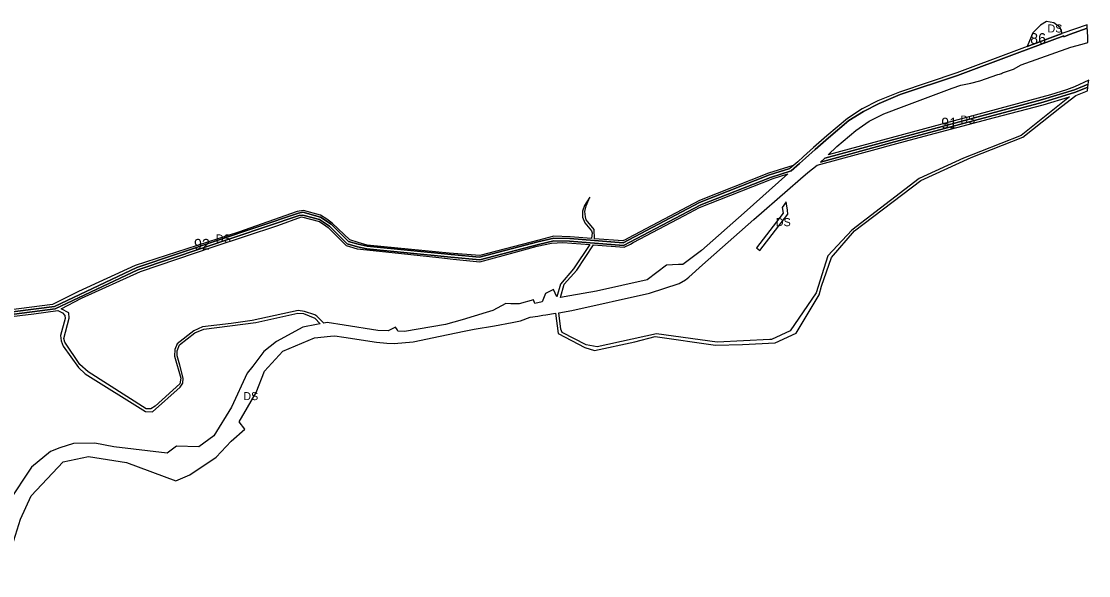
# Model space of a CAD drawing. Extents: x -477304 to -465641, y -1159113 to -1149285.
# Drawn here: x -466842 to -465641, y -1153111 to -1152488 of the extents above; entities that cross this region are included whole.
import ezdxf

# ---------------------------------------------------------------- set-up
doc = ezdxf.new("R2010")
doc.units = 0
for name, color, linetype in [('14', 7, 'Continuous'), ('35', 7, 'Continuous'), ('60', 7, 'Continuous')]:
    doc.layers.add(name, color=color, linetype=linetype)

msp = doc.modelspace()

# ---------------------------------------------------------------- linework, layer by layer
at = {"layer": '14'}
for p, q in [((-465710.6, -1152516.1), (-465671.1, -1152501.3)), ((-465643, -1152494.7), (-465643.1, -1152491.6)), ((-465669.3, -1152505.1), (-465662.8, -1152502.6)), ((-465669.2, -1152503.8), (-465669.3, -1152505.1)), ((-465642.2, -1152561.6), (-465641.9, -1152558.2)), ((-465938.3, -1152641.5), (-465943.1, -1152645.9))]:
    msp.add_line(p, q, dxfattribs=at)
for points in [[(-465671.1, -1152501.3), (-465673.6, -1152494.6), (-465680.5, -1152489.2), (-465688.7, -1152487.7), (-465695.6, -1152491.8), (-465704.3, -1152500.6), (-465710.6, -1152516.1)], [(-465643.1, -1152491.6), (-465670.3, -1152501), (-465789.9, -1152545.7), (-465854.4, -1152567.3), (-465878.5, -1152577.1), (-465896.4, -1152586.2), (-465912.9, -1152596.9), (-465936.1, -1152616.3), (-465951.1, -1152629.7), (-465962.1, -1152639.5), (-465968.7, -1152645.5), (-465977.5, -1152653.2)], [(-465662.8, -1152502.6), (-465643, -1152495.3), (-465643, -1152494.7)], [(-465976, -1152655.9), (-465966.7, -1152647.7), (-465960.1, -1152641.7), (-465949.1, -1152631.9), (-465934.2, -1152618.6), (-465911.1, -1152599.3), (-465894.9, -1152588.9), (-465877.2, -1152579.9), (-465853.4, -1152570.1), (-465788.9, -1152548.5), (-465721.8, -1152523.4), (-465669.2, -1152503.8)], [(-465641.9, -1152558.2), (-465657.3, -1152564.7), (-465693.5, -1152575.7), (-465864.7, -1152621.6), (-465938.3, -1152641.5)], [(-465943.1, -1152645.9), (-465863.9, -1152624.4), (-465692.7, -1152578.6), (-465656.2, -1152567.5), (-465642.2, -1152561.6)], [(-465977.5, -1152653.2), (-466000.4, -1152660.4), (-466079.1, -1152691.4), (-466165.2, -1152736.6), (-466225.2, -1152732), (-466243.2, -1152731.6), (-466261, -1152735.6), (-466326.7, -1152752.9), (-466358.7, -1152750), (-466453.2, -1152740.5), (-466463.2, -1152738.4), (-466474, -1152735.2), (-466493.5, -1152715.7), (-466505.4, -1152707.9), (-466525.3, -1152702.4), (-466530.3, -1152703.2), (-466712.1, -1152764.4), (-466804.8, -1152808.2), (-466914.5, -1152822.2)], [(-466914, -1152825.2), (-466803.9, -1152811.1), (-466710.9, -1152767.2), (-466529.6, -1152706.1), (-466525.4, -1152705.5), (-466506.6, -1152710.6), (-466495.4, -1152718.1), (-466475.6, -1152737.8), (-466463.9, -1152741.4), (-466453.6, -1152743.5), (-466358.9, -1152753), (-466326.5, -1152756), (-466260.3, -1152738.5), (-466242.9, -1152734.6), (-466225.4, -1152735), (-466164.6, -1152739.6), (-466077.9, -1152694.1), (-465999.4, -1152663.2), (-465976, -1152655.9)]]:
    msp.add_lwpolyline(points, dxfattribs=at)
at = {"layer": '35'}
for p, q in [((-465662.8, -1152502.6), (-465669.3, -1152505.1)), ((-465669.3, -1152505.1), (-465669.2, -1152503.8)), ((-465661.4, -1152516.9), (-465648.6, -1152513.3)), ((-465648.6, -1152513.3), (-465642.2, -1152511.5)), ((-465717.2, -1152536.5), (-465661.4, -1152516.9)), ((-465725.8, -1152541.4), (-465717.2, -1152536.5)), ((-465743.5, -1152547.6), (-465741.8, -1152547)), ((-465738.2, -1152545.7), (-465725.8, -1152541.4)), ((-465794.9, -1152563), (-465785.1, -1152559.3)), ((-465657.5, -1152561.5), (-465666.5, -1152564.7)), ((-465641.4, -1152553.9), (-465657.5, -1152561.5)), ((-465641.9, -1152558.2), (-465641.4, -1152553.9)), ((-465684.4, -1152570.4), (-465934.5, -1152637.9)), ((-465849, -1152583), (-465794.9, -1152563)), ((-465662.9, -1152572.7), (-465717.3, -1152616)), ((-465666.5, -1152564.7), (-465684.4, -1152570.4)), ((-465671.9, -1152583.3), (-465656, -1152570.9)), ((-465656, -1152570.9), (-465642.6, -1152565.8)), ((-465642.6, -1152565.8), (-465642.2, -1152561.6)), ((-465871.9, -1152591.8), (-465849, -1152583)), ((-465894.9, -1152588.9), (-465911.1, -1152599.3)), ((-465765.7, -1152600.6), (-465747.2, -1152595.8)), ((-465911.1, -1152599.3), (-465934.2, -1152618.6)), ((-465717.3, -1152616), (-465763.1, -1152633.9)), ((-465946.9, -1152649.4), (-465876.3, -1152630.3)), ((-465934.5, -1152637.9), (-465924.7, -1152628.4)), ((-465876.3, -1152630.3), (-465867, -1152627.8)), ((-465943.1, -1152645.9), (-465938.3, -1152641.5)), ((-465782.2, -1152641.6), (-465832.2, -1152664.3)), ((-465830.3, -1152666.7), (-465773.7, -1152640.9)), ((-465763.1, -1152633.9), (-465782.2, -1152641.6)), ((-465973.7, -1152649.8), (-466001.7, -1152658.4)), ((-465977.5, -1152653.2), (-465973.7, -1152649.8)), ((-465957.4, -1152657.8), (-465946.9, -1152649.4)), ((-465979.9, -1152659.3), (-466029, -1152703)), ((-465980.3, -1152677.6), (-465965.5, -1152664.6)), ((-465965.5, -1152664.6), (-465957.4, -1152657.8)), ((-465904.7, -1152723.4), (-465830.3, -1152666.7)), ((-466202.5, -1152685.4), (-466208.5, -1152694.7)), ((-465980.4, -1152700.1), (-465981.8, -1152690.7)), ((-466029, -1152703), (-466076.8, -1152745.3)), ((-466011.4, -1152745.3), (-465979.9, -1152704.6)), ((-465979.9, -1152704.6), (-465980.4, -1152700.1)), ((-466626.4, -1152741.4), (-466553.4, -1152717.2)), ((-466492.6, -1152714.6), (-466498.5, -1152710.2)), ((-466210.8, -1152707.8), (-466208.2, -1152714.4)), ((-466153.9, -1152736.4), (-466096.2, -1152706.1)), ((-466197.4, -1152732.1), (-466197.9, -1152721.7)), ((-465930.9, -1152753.1), (-465904.7, -1152723.4)), ((-466708.2, -1152768.8), (-466626.4, -1152741.4)), ((-466453.1, -1152739.4), (-466463.2, -1152736.2)), ((-466260, -1152733.8), (-466326.3, -1152751)), ((-466287.8, -1152747.6), (-466261.7, -1152740.4)), ((-466261.7, -1152740.4), (-466245.7, -1152737)), ((-466200.8, -1152731.8), (-466224.7, -1152729.9)), ((-466202.7, -1152738.7), (-466221.1, -1152765.9)), ((-466217.3, -1152767.3), (-466198.3, -1152739)), ((-466198.3, -1152739), (-466163.9, -1152741.7)), ((-466165.3, -1152734.4), (-466197.4, -1152732.1)), ((-466163, -1152733.5), (-466165.3, -1152734.4)), ((-466163.9, -1152741.7), (-466157, -1152738.1)), ((-466159.6, -1152731.6), (-466163, -1152733.5)), ((-466157, -1152738.1), (-466153.9, -1152736.4)), ((-466372.5, -1152753.4), (-466356.4, -1152755.1)), ((-466015.2, -1152742.2), (-466011.4, -1152745.3)), ((-465934.8, -1152751.4), (-465948, -1152792.9)), ((-466102.8, -1152761.2), (-466116.4, -1152761.7)), ((-466098.1, -1152761), (-466102.8, -1152761.2)), ((-466091.4, -1152775.3), (-466075.7, -1152761.4)), ((-466075.7, -1152761.4), (-466069.5, -1152755.7)), ((-466774.5, -1152799), (-466708.2, -1152768.8)), ((-466221.1, -1152765.9), (-466235.7, -1152783.2)), ((-466231.4, -1152783.4), (-466217.3, -1152767.3)), ((-466094.9, -1152778.4), (-466091.4, -1152775.3)), ((-466243.4, -1152789.3), (-466252.5, -1152793.6)), ((-466239.6, -1152797.4), (-466243.4, -1152789.3)), ((-466235.7, -1152783.2), (-466239.6, -1152797.4)), ((-466235.6, -1152798.2), (-466231.4, -1152783.4)), ((-466102.1, -1152782.6), (-466094.9, -1152778.4)), ((-466797.5, -1152811), (-466774.5, -1152799)), ((-466266, -1152800.9), (-466281.9, -1152805.4)), ((-466264.5, -1152804.8), (-466266, -1152800.9)), ((-466252.5, -1152793.6), (-466256.2, -1152802.9)), ((-466225.2, -1152796.5), (-466235.6, -1152798.2)), ((-465970.5, -1152838.3), (-465944.7, -1152795.1)), ((-466828, -1152816.6), (-466801.2, -1152813)), ((-466801.2, -1152813), (-466795.9, -1152815.5)), ((-466530.6, -1152812.8), (-466582.3, -1152824.2)), ((-466523.5, -1152813.9), (-466530.6, -1152812.8)), ((-466281.9, -1152805.4), (-466291.5, -1152805.2)), ((-466256.2, -1152802.9), (-466264.5, -1152804.8)), ((-466793, -1152821.7), (-466797.9, -1152840.9)), ((-466795.9, -1152815.5), (-466793.2, -1152818.3)), ((-466793.2, -1152818.3), (-466793, -1152821.7)), ((-466524.6, -1152816.3), (-466511.9, -1152821.6)), ((-466512.1, -1152817.8), (-466523.5, -1152813.9)), ((-466509.7, -1152819.1), (-466512.1, -1152817.8)), ((-466511.9, -1152821.6), (-466505.9, -1152827.8)), ((-466501.9, -1152827.1), (-466509.7, -1152819.1)), ((-466280.5, -1152824.6), (-466269.6, -1152820.4)), ((-466269.6, -1152820.4), (-466261, -1152819.1)), ((-466261, -1152819.1), (-466255.4, -1152818.2)), ((-466241.1, -1152815.9), (-466238.4, -1152838.6)), ((-466648, -1152835.7), (-466666.7, -1152850.2)), ((-466638.3, -1152831.3), (-466648, -1152835.7)), ((-466646.8, -1152837.9), (-466636.7, -1152834)), ((-466505.9, -1152827.8), (-466510.1, -1152828.5)), ((-466441.1, -1152835.2), (-466479, -1152829.4)), ((-466429.6, -1152835.7), (-466441.1, -1152835.2)), ((-466421.2, -1152831.5), (-466429.6, -1152835.7)), ((-466419.4, -1152834.3), (-466421.2, -1152831.5)), ((-466418.6, -1152836.2), (-466419.4, -1152834.3)), ((-466410.9, -1152836.5), (-466418.6, -1152836.2)), ((-466370.9, -1152841.6), (-466344, -1152836)), ((-466344, -1152836), (-466332.6, -1152834)), ((-466332.6, -1152834), (-466309.8, -1152829.9)), ((-466664.1, -1152851.4), (-466646.8, -1152837.9)), ((-466442.4, -1152848.6), (-466431, -1152849.4)), ((-466401.5, -1152848), (-466370.9, -1152841.6)), ((-466151.8, -1152847.9), (-466129, -1152842.2)), ((-466129, -1152842.2), (-466061.2, -1152851.7)), ((-466059.2, -1152848.5), (-466127.7, -1152839.2)), ((-466569.3, -1152859), (-466581.8, -1152875.4)), ((-466061.2, -1152851.7), (-466030.8, -1152851.2)), ((-466663.8, -1152874.2), (-466667, -1152863.7)), ((-466659.9, -1152888.8), (-466663.8, -1152874.2)), ((-466588, -1152883.4), (-466605.7, -1152921.7)), ((-466581.8, -1152875.4), (-466588, -1152883.4)), ((-466694.6, -1152926.9), (-466663.6, -1152899.1)), ((-466605.7, -1152921.7), (-466625.6, -1152953.9)), ((-466597.1, -1152938.2), (-466587.6, -1152921.8)), ((-466590.6, -1152946.1), (-466597.1, -1152938.2)), ((-466625.6, -1152953.9), (-466642.5, -1152966.2)), ((-466677.9, -1152973.4), (-466737.9, -1152966.2)), ((-466667.6, -1152965.4), (-466677.9, -1152973.4)), ((-466642.5, -1152966.2), (-466667.6, -1152965.4)), ((-466795.2, -1152983), (-466766.7, -1152976.9)), ((-466766.7, -1152976.9), (-466723.7, -1152983.7)), ((-466652.5, -1152997.5), (-466622.9, -1152977.8)), ((-466831.1, -1153021.2), (-466795.2, -1152983)), ((-466723.7, -1152983.7), (-466668.5, -1153004.5)), ((-466668.5, -1153004.5), (-466652.5, -1152997.5))]:
    msp.add_line(p, q, dxfattribs=at)
for points in [[(-465642.8, -1152497.9), (-465643, -1152495.3), (-465662.8, -1152502.6)], [(-465642.2, -1152511.5), (-465642.4, -1152506.6), (-465642.8, -1152497.9)], [(-465669.2, -1152503.8), (-465721.8, -1152523.4), (-465788.9, -1152548.5), (-465853.4, -1152570.1)], [(-465785.1, -1152559.3), (-465774, -1152557.1), (-465763.9, -1152554.6), (-465743.5, -1152547.6)], [(-465741.8, -1152547), (-465739.3, -1152546.2), (-465738.2, -1152545.7)], [(-465938.3, -1152641.5), (-465864.7, -1152621.6), (-465693.5, -1152575.7), (-465657.3, -1152564.7), (-465641.9, -1152558.2)], [(-465642.2, -1152561.6), (-465656.2, -1152567.5), (-465692.7, -1152578.6), (-465863.9, -1152624.4), (-465943.1, -1152645.9)], [(-465853.4, -1152570.1), (-465877.2, -1152579.9), (-465894.9, -1152588.9)], [(-465747.2, -1152595.8), (-465692.5, -1152581.5), (-465662.9, -1152572.7)], [(-465773.7, -1152640.9), (-465715.6, -1152618.1), (-465671.9, -1152583.3)], [(-465924.7, -1152628.4), (-465903.5, -1152610.4), (-465888.4, -1152600.1), (-465871.9, -1152591.8)], [(-465867, -1152627.8), (-465837.6, -1152619.7), (-465765.7, -1152600.6)], [(-465934.2, -1152618.6), (-465949.1, -1152631.9), (-465960.1, -1152641.7)], [(-465960.1, -1152641.7), (-465966.7, -1152647.7), (-465976, -1152655.9)], [(-465976, -1152655.9), (-465999.4, -1152663.2), (-466077.9, -1152694.1), (-466164.6, -1152739.6), (-466225.4, -1152735), (-466242.9, -1152734.6), (-466260.3, -1152738.5), (-466326.5, -1152756), (-466358.9, -1152753), (-466453.6, -1152743.5), (-466463.9, -1152741.4), (-466475.6, -1152737.8), (-466495.4, -1152718.1), (-466506.6, -1152710.6), (-466525.4, -1152705.5), (-466529.6, -1152706.1), (-466710.9, -1152767.2), (-466803.9, -1152811.1), (-466914, -1152825.2), (-466981, -1152837.6), (-467040.2, -1152843.9), (-467040.7, -1152844)], [(-467040.2, -1152840.8), (-466981.4, -1152834.6), (-466914.5, -1152822.2), (-466804.8, -1152808.2), (-466712.1, -1152764.4), (-466530.3, -1152703.2), (-466525.3, -1152702.4), (-466505.4, -1152707.9), (-466493.5, -1152715.7), (-466474, -1152735.2), (-466463.2, -1152738.4), (-466453.2, -1152740.5), (-466358.7, -1152750), (-466326.7, -1152752.9), (-466261, -1152735.6), (-466243.2, -1152731.6), (-466225.2, -1152732), (-466165.2, -1152736.6), (-466079.1, -1152691.4), (-466000.4, -1152660.4), (-465977.5, -1152653.2)], [(-466001.7, -1152658.4), (-466079.3, -1152689), (-466159.6, -1152731.6)], [(-466096.2, -1152706.1), (-466079.1, -1152697.1), (-465996.3, -1152664.5), (-465979.9, -1152659.3)], [(-465832.2, -1152664.3), (-465908, -1152722.4), (-465934.8, -1152751.4)], [(-466069.5, -1152755.7), (-466018, -1152710.4), (-465980.3, -1152677.6)], [(-466197.9, -1152721.7), (-466204.9, -1152713.3), (-466206.7, -1152710.7), (-466207.5, -1152707.5), (-466208.1, -1152701.5), (-466206.6, -1152695.1), (-466202.5, -1152685.4)], [(-465981.8, -1152690.7), (-465986.3, -1152696.9), (-465985, -1152703.5), (-466015.2, -1152742.2)], [(-466498.5, -1152710.2), (-466505.4, -1152705.7), (-466524.6, -1152700.4), (-466531.7, -1152701.4), (-466597.9, -1152724.7), (-466714, -1152762.3)], [(-466208.5, -1152694.7), (-466210.7, -1152701), (-466210.8, -1152707.8)], [(-466553.4, -1152717.2), (-466526.9, -1152707.6), (-466506.7, -1152712.6), (-466499.5, -1152717.7)], [(-466463.2, -1152736.2), (-466472.7, -1152733.2), (-466492.6, -1152714.6)], [(-466208.2, -1152714.4), (-466200.9, -1152723.1), (-466200.1, -1152725.6), (-466200.8, -1152731.8)], [(-466499.5, -1152717.7), (-466496.9, -1152719.5), (-466476.8, -1152739.6)], [(-466224.7, -1152729.9), (-466243, -1152729.3), (-466260, -1152733.8)], [(-466476.8, -1152739.6), (-466464.4, -1152743.3), (-466424.9, -1152747.7), (-466372.5, -1152753.4)], [(-466326.3, -1152751), (-466360.8, -1152748.3), (-466453.1, -1152739.4)], [(-466245.7, -1152737), (-466232.9, -1152736.5), (-466202.7, -1152738.7)], [(-466356.4, -1152755.1), (-466326.3, -1152758.1), (-466287.8, -1152747.6)], [(-466076.8, -1152745.3), (-466089.1, -1152754.4), (-466098.1, -1152761)], [(-465944.7, -1152795.1), (-465941.9, -1152785.4), (-465930.9, -1152753.1)], [(-466714, -1152762.3), (-466777.8, -1152791.4), (-466806.9, -1152806.1), (-466891.8, -1152816.9)], [(-466116.4, -1152761.7), (-466138, -1152778.5), (-466195.1, -1152790.9), (-466225.2, -1152796.5)], [(-466237.5, -1152815.3), (-466223, -1152812.7), (-466135.3, -1152793.3), (-466102.1, -1152782.6)], [(-465948, -1152792.9), (-465977.1, -1152835.8), (-465998.3, -1152845.3), (-466000.1, -1152845.4), (-466059.2, -1152848.5)], [(-466776.3, -1152873.4), (-466793.1, -1152848.4), (-466794.5, -1152844.3), (-466788.4, -1152821.6), (-466788.6, -1152815.4), (-466797.5, -1152811)], [(-466291.5, -1152805.2), (-466296.9, -1152805.1), (-466311.8, -1152812.8), (-466319.2, -1152815.1)], [(-467020, -1152844.3), (-466982.1, -1152839.9), (-466900.7, -1152825.3), (-466828, -1152816.6)], [(-466582.3, -1152824.2), (-466606.1, -1152827.5), (-466638.3, -1152831.3)], [(-466636.7, -1152834), (-466578.5, -1152826.5), (-466530.9, -1152815.7), (-466524.6, -1152816.3)], [(-466319.2, -1152815.1), (-466346.1, -1152823.4), (-466365, -1152828.5), (-466410.9, -1152836.5)], [(-466309.8, -1152829.9), (-466289.9, -1152826.3), (-466280.5, -1152824.6)], [(-466255.4, -1152818.2), (-466252.2, -1152817.7), (-466241.1, -1152815.9)], [(-466233.7, -1152837.4), (-466235.2, -1152833.9), (-466237.5, -1152815.3)], [(-466510.1, -1152828.5), (-466525.3, -1152831.4), (-466554.9, -1152847.5), (-466569.3, -1152859)], [(-466479, -1152829.4), (-466498.2, -1152826.5), (-466501.9, -1152827.1)], [(-466127.7, -1152839.2), (-466194.5, -1152853.7), (-466206.6, -1152851.6), (-466233.7, -1152837.4)], [(-466797.9, -1152840.9), (-466797.4, -1152846.9), (-466795.1, -1152852.8)], [(-466568.6, -1152881.2), (-466547.9, -1152858.4), (-466512.4, -1152843.4), (-466494.5, -1152841.7)], [(-466494.5, -1152841.7), (-466489.4, -1152841.3), (-466479.5, -1152842.9), (-466442.4, -1152848.6)], [(-466431, -1152849.4), (-466422.8, -1152850), (-466401.5, -1152848)], [(-466238.4, -1152838.6), (-466208.2, -1152854.4), (-466197.3, -1152857.7), (-466151.8, -1152847.9)], [(-466030.8, -1152851.2), (-465994.2, -1152849.3), (-465970.5, -1152838.3)], [(-466795.1, -1152852.8), (-466777.9, -1152876.9), (-466770.2, -1152884.2), (-466702.6, -1152926.5), (-466694.6, -1152926.9)], [(-466666.7, -1152850.2), (-466669.6, -1152856.6), (-466669.9, -1152864), (-466662.8, -1152889)], [(-466667, -1152863.7), (-466667, -1152858.1), (-466664.1, -1152851.4)], [(-466691.5, -1152920.5), (-466696.5, -1152923.5), (-466701.6, -1152923.3), (-466767.1, -1152881.7), (-466776.3, -1152873.4)], [(-466587.6, -1152921.8), (-466577.8, -1152904.9), (-466568.6, -1152881.2)], [(-466662.8, -1152889), (-466663.9, -1152895.4), (-466691.5, -1152920.5)], [(-466663.6, -1152899.1), (-466660.6, -1152894.7), (-466659.9, -1152888.8)], [(-466622.9, -1152977.8), (-466605.9, -1152959.7), (-466590.6, -1152946.1)], [(-466783.3, -1152962.3), (-466798.8, -1152967.1), (-466809.2, -1152971.3), (-466830.7, -1152988.9), (-466856.5, -1153028), (-466863.1, -1153038.4), (-466874.7, -1153068.8)], [(-466737.9, -1152966.2), (-466759.5, -1152961.9), (-466783.3, -1152962.3)], [(-466853.1, -1153111), (-466852.6, -1153077.3), (-466843, -1153047.3), (-466831.1, -1153021.2)]]:
    msp.add_lwpolyline(points, dxfattribs=at)

# ---------------------------------------------------------------- texts
at = {"layer": '14'}
for p in [(-465687.7, -1152500.2), (-465785.8, -1152602.6), (-466623.3, -1152736.3)]:
    msp.add_text('DS', height=9, dxfattribs=at).set_placement(p)
at = {"layer": '35'}
for p in [(-465993.3, -1152718), (-466592.4, -1152913.6)]:
    msp.add_text('DS', height=9, dxfattribs=at).set_placement(p)
at = {"layer": '60'}
for s, p in [('86', (-465707.2, -1152513)), ('91', (-465807.3, -1152608.1)), ('92', (-466647.9, -1152744.3))]:
    msp.add_text(s, height=12, dxfattribs=at).set_placement(p)

doc.saveas('drawing.dxf')
